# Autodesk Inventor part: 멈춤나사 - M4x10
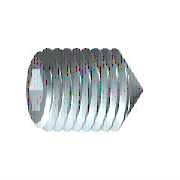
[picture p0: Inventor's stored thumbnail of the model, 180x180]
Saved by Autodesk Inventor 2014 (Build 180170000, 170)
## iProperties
Created: 2012-02
Part Number: 멈춤나사 - M4x10
Material: 강철, 연강
Description: 6각 소켓 머리 없는 멈춤 나사
Document SubType Name: Modeling
Standard: KS B 1028
Designer: mduedu
Standards Organization: KS
Language: ko-KR
Size Designation: 원추점 M4x10
Categories: <MemberInstance><Categories><Category DisplayName="조임쇠" InternalName="e4da775c-781d-43d5-af7c-5136215cf5a6" Mnemonic="FSTN"><Category DisplayName="볼트" InternalN
Density: 7.86 g/cm^3
Mass: 0.792069 g
Surface Area: 1.48192 cm^2
Volume: 0.100772 cm^3
Appearance: Steel
Author: mduedu
IsCustomPart: 1
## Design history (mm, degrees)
sketch "스케치1"
  geometry: L1 (0, 0)-(6.833, 0); L2 (10, 1.155)-(10, 2); L3 (10, 2)-(0, 2); L4 (10, 1.155)-(7.5, 1.155); L5 (7.5, 1.155)-(6.833, 0); L6 (0, -0.4)-(0, 2.4) reference; L7 (0, 2)-(0, 0)
  constraints: 13 end point, 3 parallel, 1 collinear, 1 perpendicular, 1 point on line
  dimensions: "d0" = 2.5 distance of L2.start L4.end (= INTI); "d1" = 60 deg angle of L5 L1; "d2" = 4 diameter of L3 L1 (= NND); "d3" = 2.3094 diameter of L4 L1 (= 1.1547 x SW); "d5" = 10 distance from line of L2 L3.end (= NLG)
revolve "본체" sketch "스케치1" stored, may be unused: angle "d6" = 90 deg
sketch "스케치2"
  geometry: L1 (-0.577, 1)-(0.577, 1); L2 (0.577, 1)-(1.155, 0); L3 (1.155, 0)-(0.577, -1); L4 (0.577, -1)-(-0.577, -1); L5 (-0.577, -1)-(-1.155, 0); L6 (-1.155, 0)-(-0.577, 1); 3 further points
  constraints: 12 end point, 1 coincident, 1 horizontal, 13 other
extrude "슬롯" join sketch "스케치2" taper "d7" = 0 deg; stored distance "d21" = 10
workaxis "Work Axis1"
workplane "Work Plane1"
sketch "스케치4"
  geometry: L1 (-5, 0.2)-(-3.2, 2) reference; L2 (-5, -0.2)-(-3.2, -2) reference; L3 (-3.2, 2)-(-5.2, 0); L4 (-3.2, -2)-(-5.2, 0); 2 further points
  constraints: 4 end point, 2 collinear, 1 coincident
body "Solid1"
feature "스레드" dims "d12" = 10 (= NLG), "d13" = 0
chamfer "모따기1" distance "d8" = 1.8 (computed from NND, SPD, FAWI); stored, may be unused: angle "d9" = 45 deg (= FAWI), second distance "d34" = 1.8 (computed from NND, SPD, FAWI)
chamfer "모따기2" distance "d10" = 0.42941 (= -0.5 x GD1 + 0.5 x NND); stored, may be unused: angle "d11" = 45 deg (= FAWI), second distance "d35" = 0.42941 (= -0.5 x GD1 + 0.5 x NND)
other parameters: "NND" = 4 [user parameter; used in 5 equation terms], "NLG" = 10 [user parameter; used in 2 equation terms], "INTI" = 2.5 [user parameter; used in 1 equation term], "FAWI" = 45 deg [user parameter; used in 4 equation terms], "SW" = 2 [user parameter; used in 2 equation terms], "GD1" = 3.14117 (= THREADDIA - 1.2269 x PTC) [user parameter; used in 2 equation terms], "d4" = 0, "FAWI1" = 45 deg [user parameter], "SPD" = 0.4 [user parameter; used in 2 equation terms], "d36" = 0, "d37" = 0, "GUL" = 0.42941 (= 0.61345 x PTC) [user parameter], "TPU" = 14.28571 (computed from PTC) [user parameter], "TOA" = 30 deg [user parameter], "THREADDIA" = 4 [user parameter; used in 1 equation term], "PTC" = 0.7 [user parameter; used in 4 equation terms], "GAL" = 0.42941 (= 0.61345 x PTC) [user parameter], "E0" = 2.31 (= 1.155 x SW) [user parameter]
